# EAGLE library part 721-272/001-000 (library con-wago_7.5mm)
Serie 721, Stiftleiste mit geraden Einlötstiften / Series 721, Male connector with straight solder pins Polzahl / Pole No.: 12 Rastermaß / Pitch: 7.5 mm Bemessungsspannung / Rated Voltage: 630 V Nennstrom / Nominal Current: 16 A Lötstiftlänge: / Solder Pin Length: 5 mm Farbe / Color: lichtgrau / light gray Stand: 01.01.2012. Die jeweils aktuellen Daten zu diesem Artikel finden Sie in unserem Produktkatalog, den Sie unter www.wago.com einsehen können. As of: 01/01/2012. Please find the newest data for this article in our product catalogue, which can be viewed under www.wago.com.
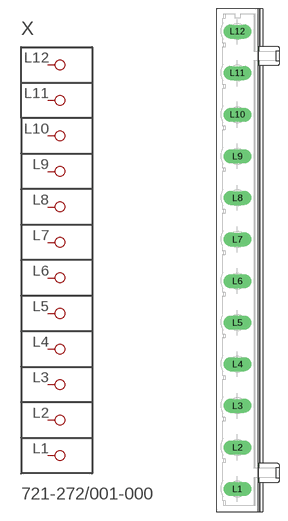
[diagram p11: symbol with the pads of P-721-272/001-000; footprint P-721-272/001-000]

Designator prefix X

## 721-272/001-000  [P-721-272/001-000]
L1  P1
L2  P2
L3  P3
L4  P4
L5  P5
L6  P6
L7  P7
L8  P8
L9  P9
L10  P10
L11  P11
L12  P12

## Footprint P-721-272/001-000 (pad centres in mm)
drill 1.7 long: L1 -1.9,-41.25; L2 -1.9,-33.75; L3 -1.9,-26.25; L4 -1.9,-18.75; L5 -1.9,-11.25; L6 -1.9,-3.75; L7 -1.9,3.75; L8 -1.9,11.25; L9 -1.9,18.75; L10 -1.9,26.25; L11 -1.9,33.75; L12 -1.9,41.25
